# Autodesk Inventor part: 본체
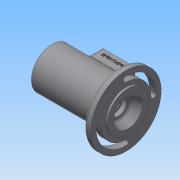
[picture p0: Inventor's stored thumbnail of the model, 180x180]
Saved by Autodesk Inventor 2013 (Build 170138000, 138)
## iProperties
Created: 2017-05
Part Number: 본체
Material: 일반
Document SubType Name: Modeling
Designer: Administrator
Density: 1 g/cm^3
Author: Administrator
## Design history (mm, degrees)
sketch "스케치1"
  geometry: L1 (-56, 0)-(-56, 21); L2 (-56, 31)-(46, 31); L3 (46, 31)-(46, 53); L4 (46, 53)-(56, 53); L5 (56, 53)-(56, 31); L6 (56, 31)-(59, 31); L7 (59, 31)-(59, 22); L8 (59, 0)-(-56, 0); L9 (-47, 21)-(-47, 24); L10 (-47, 24)-(-44, 24); L11 (-44, 24)-(-44, 20); L12 (-44, 20)-(-35, 20); L13 (-35, 20)-(-35, 17.5); L14 (-35, 17.5)-(-31.75, 17.5); L15 (-31.75, 17.5)-(-31.75, 18.5); L16 (-31.75, 18.5)-(-30, 18.5); L17 (-30, 18.5)-(-30, 17.5); L18 (-30, 17.5)-(-19, 17.5); L19 (-19, 17.5)-(-19, 26); L20 (-19, 26)-(19, 26); L21 (19, 26)-(19, 17.5); L22 (19, 17.5)-(30, 17.5); L23 (35, 10)-(37.7, 10); L24 (37.7, 10)-(37.7, 12.5); L25 (37.7, 12.5)-(45, 12.5); L26 (45, 12.5)-(45, 16); L27 (45, 16)-(59, 22); L28 (30, 16.5)-(30, 17.5); L29 (-47, 21)-(-56, 21); L30 (30, 16.5)-(35, 16.5); L31 (35, 16.5)-(35, 10); L32 (-56, 21)-(-56, 31); L33 (59, 22)-(59, 0); 1 further point
  constraints: 66 end point, 16 parallel, 7 perpendicular, 4 collinear, 3 horizontal, 3 vertical, 1 horizontal alignment
  dimensions: "d0" = 62 diameter of L6 L8; "d2" = 106 diameter of L4 L8; "d4" = 115 distance of L8.start L1.start; "d5" = 3 distance of L5.end L6.end; "d7" = 56 distance from line of point (0, 0) L1; "d8" = 25 diameter of L25 L8; "d9" = 20 diameter of L23 L8; "d11" = 32 diameter of L26.end L8; "d12" = 44 diameter of L7.end L8; "d14" = 14 horizontal distance of L26.end L7.end; "d19" = 38 distance of L19.end L20.end; "d20" = 52 diameter of L20 L8; "d21" = 11 distance of L17.end L18.end; "d22" = 1.75 distance of L15.end L16.end; "d23" = 37 diameter of L16 L8; "d24" = 35 diameter of L18 L8; "d25" = 3 distance of L9.end L10.end; "d26" = 12 distance between parallel lines of L1 L11; "d27" = 48 diameter of L10 L8; "d28" = 42 diameter of L29 L8; "d29" = 40 diameter of L12 L8; "d30" = 21 distance between parallel lines of L1 L13; "d35" = 11 distance of L21.end L22.end; "d36" = 33 diameter of L30 L8; "d37" = 5 distance of L28.start L30.end; "d38" = 2.7 distance of L23.start L23.end; "d40" = 26 distance from line of L1 L17.end; "d101" = 13 distance between parallel lines of L7 L3
revolve "회전1" sketch "스케치1" stored, may be unused: angle "d41" = 90 deg
feature "스레드1" dims "d42" = 10, "d43" = 0
node "작업 평면1"
sketch "스케치2"
  geometry: L1 (-25, 20)-(25, 20); L2 (25, 20)-(25, -20); L3 (25, -20)-(-25, -20); L4 (-25, -20)-(-25, 20); L5 (-16, 11)-(16, 11); L6 (16, 11)-(16, -11); L7 (16, -11)-(-16, -11); L8 (-16, -11)-(-16, 11); 5 further points
  constraints: 16 end point, 4 midpoint, 4 parallel, 2 horizontal, 2 horizontal alignment, 2 perpendicular, 2 vertical alignment
  dimensions: "d45" = 50 distance of L2.end L3.end; "d47" = 40 distance of L1.end L2.end; "d59" = 22 distance of L5.end L6.end; "d60" = 32 distance of L5.start L5.end
extrude "돌출1" join sketch "스케치2" stored distance "d48" = 10; taper "d49" = 0 deg
sketch "스케치3"
  geometry: A1 r 41.5 centre (0, 0) between (0, 41.5) and (-41.5, 0); A2 r 4 centre (0, 41.5) between (0, 45.5) and (0, 37.5); A3 r 4 centre (-41.5, 0) between (-37.5, 0) and (-45.5, 0); A4 r 4 centre (41.5, 0) between (37.5, 0) and (45.5, 0); A5 r 4 centre (0, -41.5) between (0, -45.5) and (0, -37.5); A6 r 37.5 centre (0, 0) between (37.5, 0) and (0, 37.5); A7 r 37.5 centre (0, 0) between (-37.5, 0) and (0, -37.5); A8 r 45.5 centre (0, 0) between (45.5, 0) and (0, 45.5); A9 r 45.5 centre (0, 0) between (-45.5, 0) and (0, -45.5); 1 further point
  constraints: 20 point on circle, 9 centre point, 5 tangent, 3 coincident, 2 horizontal alignment, 2 vertical alignment
  dimensions: "d91" = 83 diameter of A1; "d94" = 8 diameter of A4; "d95" = 4 radius of A5; "d96" = 4 radius of A2
extrude "돌출2" cut sketch "스케치3" stored distance "d57" = 10; taper "d58" = 0 deg
extrude "돌출3" cut sketch "스케치2" stored distance "d61" = 10; taper "d62" = 0 deg
sketch "스케치5"
  geometry: 2 further points
  dimensions: "d63" = 15.5 vertical distance of point (0, 0) point (-20.5, 15.5); "d64" = 20.5 horizontal distance of point (0, 0) point (-20.5, 15.5)
hole "구멍1" sketch "스케치5" at (-20.5, 15.5) diameter "d65" = 2.459; stored, may be unused: countersink angle "d69" = 90 deg, drill point angle "d71" = 118 deg; dims "d66" = 6, "d67" = 4, "d68" = 2, "d70" = 8
chamfer "모따기1" distance "d78" = 1; stored, may be unused: second distance "d79" = 2, angle "d80" = 45 deg
fillet "모깎기1" dims "d81" = 3
chamfer "모따기2" distance "d82" = 0.7; stored, may be unused: second distance "d83" = 2, angle "d84" = 30 deg
fillet "모깎기2" dims "d85" = 3
fillet "모깎기3" dims "d86" = 0.3
chamfer "모따기3" distance "d87" = 1; stored, may be unused: second distance "d88" = 2, angle "d89" = 30 deg
sketch "스케치10"
  geometry: L1 (44, 0)-(0, 0) reference; L2 (-34, -75)-(-34, -13) reference; 2 further points
  constraints: 1 other
  dimensions: "d97" = 56 distance from line of L2 point (22, -8); "d98" = 8 distance from line of L1 point (22, -8)
feature "엠보싱1" sketch "스케치10" dims "d99" = 0.5, "d100" = 0
node "솔리드1"
pattern_linear "직사각형 패턴1" dims "d74" = 31, "d77" = 41
other parameters: "d44" = 44, "d56" = 91, "d92" = 75, "d93" = 91
